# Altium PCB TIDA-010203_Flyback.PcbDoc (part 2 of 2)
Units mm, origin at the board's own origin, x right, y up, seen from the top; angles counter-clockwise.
Board outline 58 x 45 mm, 2 copper layers (Top Layer, Bottom Layer), stack 1.646 mm thick; 65 components, 31 nets, 152 pads, 52 vias.
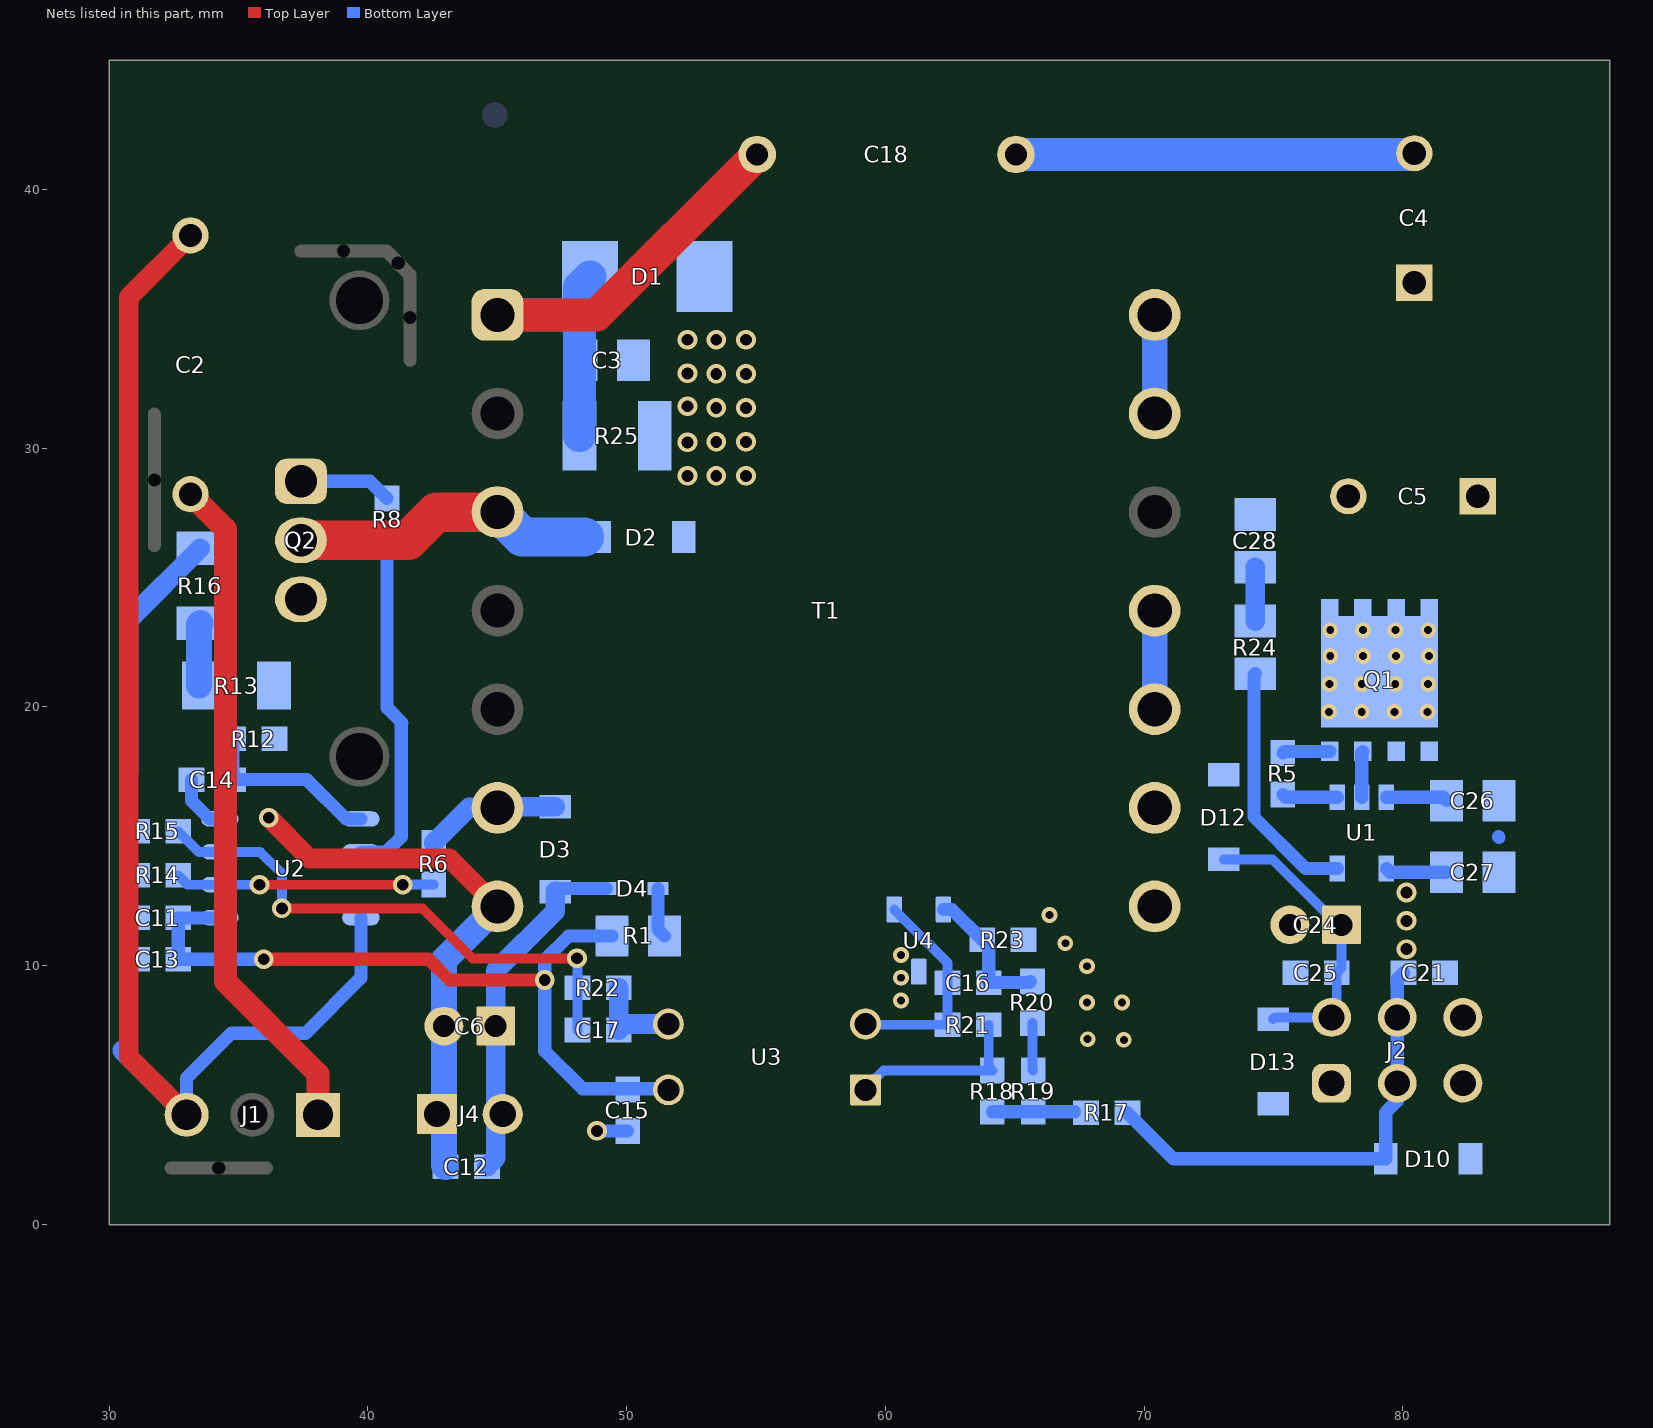
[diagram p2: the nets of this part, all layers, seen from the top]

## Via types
v1: diameter 0.762, hole 0.457, Top Layer to Bottom Layer, tented both sides, 26 vias
v2: diameter 0.61, hole 0.305, Top Layer to Bottom Layer, tented both sides, 26 vias

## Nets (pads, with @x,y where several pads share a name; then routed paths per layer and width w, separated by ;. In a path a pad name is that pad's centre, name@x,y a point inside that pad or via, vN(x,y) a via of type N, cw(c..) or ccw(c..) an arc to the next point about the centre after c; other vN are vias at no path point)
5V_ISO: C24.1 C25.1 D12.1 D13.1 J2.2 | length 11.6
  Bottom Layer w0.381: D12.1@73.076,14.111 74.966,14.111 77.494,11.582 C24.1@77.632,11.582 77.632,9.915 C25.1@77.445,9.728 77.445,8.204 J2.2@77.241,8.001 75.045,8.001 D13.1@74.981,7.937
12V: C6.1 C12.1 D3.1 D4.2 J4.2 | length 13.7
  Bottom Layer w0.508: D3.1@47.244,12.866 47.357,12.979 D4.2@49.216,12.979
  Bottom Layer w0.762: C12.1@44.602,2.235 44.942,2.575 C6.1@44.942,7.671 44.942,9.814 47.244,12.116 D3.1@47.244,12.866
12V_ISO: C4.1 C5.1 C21.1 C27.1 D10.1 J2.3 J2.4 R17.1 T1.13 T1.14 U1.4 | length 24.4
  Bottom Layer w0.508: R17.1@69.355,4.318 71.133,2.54 D10.1@79.338,2.54 79.338,4.332 79.781,4.775 J2.3@79.781,5.461 J2.4@79.781,8.001 79.781,9.487 C21.1@80.023,9.728 ; U1.4@79.36,13.763 79.509,13.614 C27.1@81.686,13.614
  Bottom Layer w1: T1.13@70.409,31.344 T1.14@70.409,35.154
  other v1: 80.137,10.643 80.137,11.735 80.137,12.827
NetC3_2: C3.2 D1.1 D2.1 R25.1
  other v1: 52.349,28.931 53.467,28.931 54.61,28.931 52.349,30.226 53.467,30.245 54.61,30.245 53.467,31.559 54.61,31.559 52.349,31.623 53.467,32.874 54.61,32.874 52.349,32.893 52.349,34.188 53.467,34.188 54.61,34.188
NetC14_1: C14.1 R12.1 U2.5 | length 7.2
  Bottom Layer w0.508: R12.1@34.785,18.771 C14.1@34.785,17.196 37.643,17.196 39.167,15.672 U2.5@39.733,15.672
NetC16_1: C16.1 R20.1 R23.1 U4.2 | length 5.4
  Bottom Layer w0.508: U4.2@62.24,12.173 62.567,12.173 R23.1@63.741,10.998 63.995,10.744 C16.1@63.995,9.347 65.57,9.347 R20.1@65.608,9.385
NetC16_2: C16.2 R21.1 U3.2 U4.1 | length 8.5
  Bottom Layer w0.381: U3.2@59.233,7.747 59.258,7.722 R21.1@62.395,7.722 C16.2@62.395,9.347 62.395,10.118 U4.1@60.34,12.173
NetC17_2: C17.2 R22.2 U3.3 | length 3.6
  Bottom Layer w0.762: R22.2@49.695,9.144 C17.2@49.695,7.518 49.924,7.747 U3.3@51.613,7.747
NetC26_1: C26.1 U1.3 | length 2.4
  Bottom Layer w0.508: U1.3@79.36,16.513 81.556,16.513 C26.1@81.686,16.383
NetC28_1: C28.1 R24.1 | length 2.1
  Bottom Layer w0.762: R24.1@74.295,23.317 C28.1@74.295,25.4
NetD2_2: D2.2 Q2.2 T1.3 | length 11.8
  Top Layer w1.524: Q2.2@37.414,26.441 41.554,26.441 42.647,27.534 T1.3@45.009,27.534
  Bottom Layer w1.524: T1.3@45.009,27.534 45.974,26.568 48.361,26.568
NetD4_1: D4.1 R1.1 | length 1.9
  Bottom Layer w0.508: D4.1@51.216,12.979 51.216,11.395 R1.1@51.46,11.151
NetD12_2: D12.2 T1.9
NetQ1_4: Q1.4 R5.2 | length 1.8
  Bottom Layer w0.508: R5.2@75.362,18.224 75.421,18.284 Q1.4@77.178,18.284
NetQ1_5: Q1.5 Q1.6 Q1.7 Q1.8 Q1.9 R24.2 T1.10 T1.11 U1.5 | length 13.4
  Bottom Layer w0.508: R24.2@74.295,21.285 74.244,21.234 74.244,15.748 76.229,13.763 U1.5@77.46,13.763
  Bottom Layer w1: T1.10@70.409,19.914 T1.11@70.409,23.724
  other v2: 77.14,19.812 78.41,19.812 79.68,19.812 80.95,19.812 77.165,20.883 78.41,20.883 79.705,20.883 80.976,20.883 77.191,21.971 78.461,21.971 79.731,21.971 81.001,21.971 77.191,22.968 78.452,22.968 79.714,22.968 80.976,22.968
NetQ2_1: Q2.1 R8.2 | length 3.6
  Bottom Layer w0.508: Q2.1@37.414,28.721 40.074,28.721 R8.2@40.742,28.054
NetQ2_3: Q2.3 R12.2 R13.2
NetR5_1: R5.1 U1.1 | length 2.1
  Bottom Layer w0.508: R5.1@75.362,16.624 75.473,16.513 U1.1@77.46,16.513
NetR6_1: R6.1 R14.2 U2.2 | length 10
  Top Layer w0.381: v1(35.814,13.132) v1(41.351,13.132)
  Bottom Layer w0.381: R14.2@32.674,13.489 33.032,13.132 U2.2@34.283,13.132 v1(35.814,13.132) v1@35.839,13.132 ; v1(41.351,13.132) 41.364,13.145 R6.1@42.545,13.145
NetR8_1: R8.1 U2.6 | length 13.5
  Bottom Layer w0.508: U2.6@39.733,14.402 40.716,14.402 41.289,14.975 41.289,19.343 41.326,19.38 40.742,19.964 R8.1@40.742,26.454
NetR13_1: R13.1 R16.2 | length 2.4
  Bottom Layer w1.016: R13.1@33.475,20.828 33.475,23.186 R16.2@33.528,23.239
NetR17_2: R17.2 R18.1 R19.2 | length 3.2
  Bottom Layer w0.508: R18.1@64.135,4.356 R19.2@65.71,4.356 R17.2@67.31,4.356
NetR18_2: R18.2 R21.2 U3.1 | length 7.1
  Bottom Layer w0.381: U3.1@59.233,5.207 59.182,5.207 59.931,5.956 R18.2@64.135,5.956 63.995,6.096 R21.2@63.995,7.722
NetR19_1: R19.1 R20.2 | length 1.8
  Bottom Layer w0.381: R20.2@65.684,7.785 65.684,5.982 R19.1@65.71,5.956
PGND: C2.2 C6.2 C11.2 C12.2 C13.2 C14.2 C15.2 J1.1 J4.1 R14.1 R15.1 R16.1 T1.7 U2.4 | length 60.4
  Top Layer w0.762: v1(36.17,15.723) 37.744,14.148 43.155,14.148 T1.7@45.009,12.294
  Top Layer w0.889: C2.2@33.147,28.223 34.493,26.877 34.493,9.398 38.075,5.817 J1.1@38.075,4.242
  Bottom Layer w0.508: C14.2@33.185,17.196 33.185,16.37 33.884,15.672 U2.4@34.283,15.672 ; v1(48.857,3.62) C15.2@50.038,3.62
  Bottom Layer w0.762: 30.759,17.475 30.759,23.37 R16.1@33.528,26.139
  Bottom Layer w1.016: C12.2@43.002,2.235 42.942,2.295 C6.2@42.942,7.671 42.942,10.227 T1.7@45.009,12.294
SGND: C4.2 C5.2 C18.1 C21.2 C26.2 C27.2 C28.2 D10.2 J2.5 J2.6 Q1.1 Q1.2 Q1.3 R23.2 U1.2 U4.3 | length 17.2
  Bottom Layer w0.508: U1.2@78.41,16.513 78.41,18.237 Q1.3@78.456,18.284 ; C4.2@80.395,41.351 C4.2@80.442,41.398 ; 83.693,14.986 83.718,14.961
  Bottom Layer w1.27: C18.1@65.046,41.351 C4.2@80.395,41.351
  other v2: 69.215,7.137 67.818,7.163 67.793,8.585 69.139,8.585 60.604,8.661 60.604,9.538 67.793,9.982 60.604,10.414 66.954,10.871 66.345,11.963
SGND2: C24.2 C25.2 D13.2 J2.1 T1.8
VAUX: D3.2 R6.2 T1.6 | length 5.3
  Bottom Layer w0.762: R6.2@42.545,14.745 43.917,16.116 44.996,16.116 T1.6@45.009,16.104 45.046,16.141 D3.2@47.244,16.141
VDCBUS+: C2.1 C3.1 C18.2 D1.2 J1.3 R25.2 T1.1 U2.8 | length 73.7
  Top Layer w0.762: J1.3@32.995,4.242 30.759,6.477 30.759,35.836 C2.1@33.147,38.223
  Top Layer w1.27: T1.1@45.009,35.154 48.848,35.154 C18.2@55.046,41.351
  Bottom Layer w0.508: J1.3@32.995,4.242 32.995,5.664 34.724,7.394 37.595,7.394 39.733,9.532 U2.8@39.733,11.862
  Bottom Layer w0.762: 30.505,6.731 J1.3@32.995,4.242
  Bottom Layer w1.27: T1.1@45.009,35.154 47.981,35.154 D1.2@48.182,35.355 ; R25.2@48.182,30.48 D1.2@48.182,35.355 ; D1.2@48.59,36.627 48.182,36.218 D1.2@48.182,35.355
VDD: C11.1 C13.1 C15.1 R1.2 U2.1 U3.4 | length 29.6
  Top Layer w0.508: v1(35.98,10.25) 42.353,10.25 43.155,9.449 v1(46.838,9.449)
  Bottom Layer w0.508: U2.1@34.283,11.862 34.271,11.85 C11.1@32.675,11.85 C13.1@32.675,10.25 v1(35.98,10.25) ; R1.2@49.428,11.151 47.76,11.151 46.838,10.228 v1(46.838,9.449) 46.838,6.706 48.298,5.245 51.575,5.245 U3.4@51.613,5.207
VFB: C17.1 R15.2 R22.1 U2.3 | length 21
  Top Layer w0.381: v1(36.678,12.217) 42.113,12.217 44.044,10.287 v1(48.082,10.287)
  Bottom Layer w0.381: R15.2@32.674,15.191 33.464,14.402 U2.3@34.283,14.402 35.839,14.402 36.678,13.564 v1(36.678,12.217) ; v1(48.082,10.287) 48.095,10.274 R22.1@48.095,9.144 C17.1@48.095,7.518
pads on no net: FID1.1 HS1.1 HS1.2 J1.2 T1.2 T1.4 T1.5 T1.12

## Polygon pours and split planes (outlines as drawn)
PGND on Top Layer "PGND_L01_P012" (solid, pour order 12): 45.136,11.379 48.895,11.379 48.895,9.144 48.463,9.144 47.854,8.534 41.123,8.534 41.148,8.509 41.148,1.854 51.308,1.854 51.41,1.956 51.41,13.183 44.907,13.183 44.552,12.827 44.552,12.243
12V_ISO on Top Layer "12V_ISO_L01_P000" (solid, pour order 0): 69.19,30.455 69.19,37.516 69.266,37.592 86.487,37.592 86.487,11.227 85.217,9.957 82.245,9.957 82.245,27.965 79.781,30.429
SGND on Bottom Layer "Top Layer-No Net" (solid, pour order 2): 73.533,27.991 73.508,28.016 73.508,37.592 86.512,37.592 86.335,37.414 86.335,1.727 82.677,1.727 82.296,2.108 82.296,8.738 81.356,9.677 81.356,10.846 83.566,13.056 83.566,17.221 83.414,17.221 82.245,18.39 82.321,18.466 82.321,25.806 77.191,25.806 76.022,26.975 74.676,26.975

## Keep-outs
Keep-Out Layer:
  text ".Layer_Name" at -20.904,-46.571 h1.52

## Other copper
Top Layer:
  rectangle net NetD2_2: 41.554,25.654 45.923,27.432
  region net PGND: 42.088,15.773 46.152,13.132 46.152,12.878 46.152,12.344 44.628,12.344 43.84,13.132
  region net PGND: 42.443,13.868 44.094,12.217 44.094,12.065 44.729,12.065 44.983,12.319 42.951,14.351 42.951,14.376
  region net PGND: 36.17,15.723 36.22,15.773 42.088,15.773 43.409,14.453 43.155,14.199 43.155,14.148 37.744,14.148
  region net NetC3_2: 50.444,34.493 51.968,36.017 52.019,35.966 55.296,35.966 55.296,25.222 55.27,25.197 51.613,25.197 51.613,27.889 51.638,27.915 50.444,29.108
  region net NetD2_2: 41.377,25.806 42.342,26.772 45.212,26.772 45.212,27.381 44.882,27.711 44.78,27.61 42.215,27.61
  region net 12V_ISO: 82.372,12.116 80.67,12.116 78.816,10.262 78.816,4.623 78.791,4.597 78.791,4.496 78.791,4.013 80.874,4.013 80.874,9.042 81.305,9.347 82.55,10.16
  region net 12V_ISO: 82.692,15.875 82.448,15.875 79.502,12.929 79.502,10.465 82.169,10.465 82.956,11.252
  region net SGND: 82.296,8.865 82.296,3.378 75.514,3.378 75.514,10.185 75.463,10.236 69.088,10.236 66.319,13.005 60.249,13.005 60.249,1.346 60.325,1.27 86.258,1.27 86.258,8.839
  region net NetQ1_5: 69.139,21.438 69.139,18.796 72.898,18.796 74.994,16.7 81.407,16.7 81.407,24.994 76.2,24.994 76.175,24.968 76.175,22.606 75.413,22.606 74.244,21.438
  region net NetQ1_5: 76.2,24.994 72.111,20.904 76.175,20.904 76.276,20.803
  region net VDCBUS+: 32.614,37.821 32.614,37.567 32.868,37.313 33.63,37.313 34.722,38.405 43.459,38.405 43.739,38.125 43.739,33.96 46.253,33.96 46.228,33.985 46.228,38.659 46.177,38.659 44.526,40.31 34.392,40.31 34.366,40.284 33.096,40.284 32.156,39.345 32.156,37.719 32.487,37.389
  text ".Layer_Name" at -20.904,-46.571 h1.52
Bottom Layer:
  rectangle net SGND: 78.13,17.526 84.353,18.669
  rectangle net PGND: 30.404,9.55 31.547,17.882
  region net PGND: 33.35,16.307 31.191,16.307 31.14,16.358 31.14,16.662 33.35,16.662
  region net PGND: 33.63,16.764 34.442,15.951 33.731,15.951 33.706,15.926 33.223,16.408 33.223,16.84
  region net PGND: 33.198,25.502 33.541,25.502 31.686,23.508 31.471,23.724 31.445,23.749
  region net PGND: 33.697,27.347 30.378,23.647 30.378,23.419 30.711,23.419 30.93,23.2
  region net NetC3_2: 53.01,36.627 52.603,36.627 50.444,34.468 50.444,29.108 52.426,27.127 52.426,25.273 52.502,25.197 55.27,25.197 55.27,37.998 55.245,38.024 53.035,38.024
  region net NetD2_2: 44.882,27.711 48.565,27.711 48.565,26.848 48.463,26.949 45.796,26.949
  region net NetQ1_5: 73.749,21.882 72.161,21.641 69.139,21.285 69.139,21.082 69.19,21.031 72.898,21.031
  region net NetQ1_5: 72.542,21.361 72.466,21.285 69.139,21.285 69.139,18.847 69.113,18.821 69.139,18.796 72.898,18.796 72.898,18.898 73.914,19.914
  region net NetQ1_5: 70.409,19.914 70.942,19.914 72.746,21.717 80.112,21.717 80.645,21.184 80.645,19.228 70.409,19.228 70.18,19.456
  region net NetD12_2: 73.787,17.678 69.367,17.678 69.367,15.24 71.45,15.24 72.695,16.51 73.063,16.954 72.923,17.297 72.974,17.348
  region net PGND: 31.699,24.31 31.699,17.196 30.607,18.288 30.607,23.218
  region net PGND: 32.487,29.007 34.214,29.007 34.646,28.575 34.646,25.527 32.487,25.527 32.461,25.502
  region net NetQ2_3: 35.916,18.364 35.916,25.019 35.941,25.044 35.992,24.994 38.481,24.994 38.481,20.98 37.744,20.244 37.744,18.364
  region net SGND: 82.321,19.057 82.321,18.034 83.083,17.272 83.083,12.548 83.058,12.522 83.668,11.913 85.801,11.913 85.801,19.533 85.547,19.787
  region net 12V_ISO: 81.686,13.614 81.661,13.589 81.661,12.37 80.518,11.227 80.518,9.728 79.629,9.728 79.578,9.677 79.509,9.747 79.509,13.614
  region net SGND2: 70.358,9.601 70.358,13.284 75.59,12.319 76.276,11.633 76.276,9.601 75.844,9.601
  region net SGND2: 70.358,11.506 74.092,11.506 73.812,11.227 73.812,5.867 77.064,5.867 77.572,5.359 77.572,4.318 73.152,4.318 70.358,7.112
  region net SGND: 77.521,37.567 83.49,37.567 83.49,44.094 83.414,44.171 77.546,44.171
  region net SGND: 61.29,10.312 60.655,10.947 60.3,10.947 60.3,8.331 60.376,8.255 60.808,8.255 61.29,8.738
  region net NetQ1_5: 74.981,21.869 75.489,21.869 76.378,22.758 76.378,24.968 81.407,24.968 81.306,20.371 74.905,20.371 74.879,20.396
  region net SGND: 64.922,12.319 64.922,10.897 65.938,10.897 66.904,9.931 66.904,5.74 69.977,5.74 69.977,9.804 69.113,9.804 66.599,12.319
  region net SGND: 65.405,10.541 66.954,10.541 66.294,11.201 65.684,11.201
  region net PGND: 34.442,15.875 34.62,15.951 35.342,16.267 36.678,16.267 36.678,15.113 34.773,15.113 34.493,15.392
  region net PGND: 31.369,17.551 32.83,17.551 33.185,17.196 33.02,17.031 33.02,16.51 31.293,16.51 31.14,16.662
  text ".Layer_Name" at -20.904,-46.571 h1.52

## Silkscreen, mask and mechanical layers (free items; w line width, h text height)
Top Overlay:
  text "5V 12V RT12" at 81.001,10.795 h0.64
  text "RT5 12V RT12" at 80.391,9.474 h0.64
  text "12VDC-0.25A" at 47.066,2.032 h0.64
  text "60W_AUX_E1" at 56.49,1.295 h1.52
  text ".Layer_Name" at -20.904,-46.571 h1.52
Bottom Overlay:
  circle w0.2: c34.646,10.795 r0.205
  lines w0.152: 32.69,7.036 32.69,6.706 ; 33.02,6.706 32.69,6.706 ; 33.198,9.373 33.198,7.214 32.69,6.706
  text ".Layer_Name" at -20.904,-46.571 h1.52
Top Paste:
  text ".Layer_Name" at -20.904,-46.571 h1.52
Bottom Paste:
  text ".Layer_Name" at -20.904,-46.571 h1.52
Top Solder:
  text ".Layer_Name" at -20.904,-46.571 h1.52
  text ".Layer_Name" at -20.904,-46.571 h1.52
Bottom Solder:
  text ".Layer_Name" at -20.904,-46.571 h1.52
Drill Guide:
  text ".Layer_Name" at -20.904,-46.571 h1.52
M1 Board Outline:
  the board outline again, w0.254
M2 Board Dimensions:
  rectangle: -35.56,-31.75 -32.385,-28.575
  rectangle: -32.385,-34.925 -22.86,-31.75
  lines w0.178: -35.56,-31.75 -10.16,-31.75 ; -32.385,-34.925 -32.385,-28.575 ; -29.21,-34.925 -29.21,-28.575 ; -22.86,-34.925 -22.86,-28.575 ; -16.51,-34.925 -16.51,-28.575 ; -35.56,-34.925 -10.16,-34.925 -10.16,-28.575 -35.56,-28.575 -35.56,-34.925
M3 3D STEP Top:
  text ".Layer_Name" at -20.904,-46.571 h1.52
M4 3D STEP Bottom:
  text ".Layer_Name" at -20.904,-46.571 h1.52
M5 Assembly Top:
  circle w0.2: c42.443,2.032 r0.17
  circle w0.2: c31.521,4.039 r0.24
  lines w0.254: -42.977,-48.391 124.663,-48.391 ; -42.977,-43.227 124.714,-43.227 ; -42.977,-38.062 -42.977,-53.556 58.75,-53.556 124.714,-53.556 124.714,-38.062 -42.964,-38.062 -42.964,-53.556 -2.946,-53.556 ; 19.634,-53.556 19.634,-38.062 ; 51.816,-43.227 51.816,-38.062 ; 73.152,-43.227 73.152,-38.062 ; 88.951,-53.721 88.951,-48.569
  text "COMPONENTS MARKED 'DNP' SHOULD NOT BE POPULATED." at -6.261,-32.855 h1.52
  text "ASSEMBLY VARIANT:" at -6.274,-35.789 h1.52
  text ".VariantName" at 20.041,-35.789 h1.52
  text "PCB VIEWED FROM TOP SIDE" at -41.364,-41.419 h1.52
  text "BOARD #:" at 21.539,-41.419 h1.52
  text ".PRJ_Number" at 35.395,-41.419 h1.52
  text "REV:" at 56.845,-41.419 h1.52
  text ".PCB_Rev" at 64.249,-41.419 h1.52
  text "SVN REV:" at 78.13,-41.419 h1.52
  text ".VersionControl_RevNumber" at 90.983,-41.419 h0.76
  text ".layer_Name" at -38.075,-46.558 h1.52
  text "TID #:" at 21.539,-46.584 h1.52
  text ".TID" at 35.395,-46.584 h1.52
  text "PLOT NAME =" at -41.364,-51.799 h1.52
  text ".plot_File_Name" at -20.904,-51.799 h1.52
  text "GENERATED    :" at 21.59,-51.799 h1.52
  text ".Print_Date" at 43.675,-51.799 h1.52
  text ".Print_Time" at 62.192,-51.799 h1.52
  text "TEXAS INSTRUMENTS" at 94.31,-51.799 h1.52
M6 Assembly Bottom:
  circle w0.2: c56.617,13.868 r0.17
  circle w0.2: c35.941,11.938 r0.18
  lines w0.254: -42.989,-43.239 124.701,-43.239 ; -42.939,-48.404 124.701,-48.404 ; -7.226,-53.734 -7.226,-48.582 ; 8.572,-43.239 8.572,-38.075 ; 29.909,-43.239 29.909,-38.075 ; 62.09,-53.569 62.09,-38.075 ; 84.671,-53.569 124.689,-53.569 124.689,-38.075 -42.989,-38.075 -42.989,-53.569 22.974,-53.569 124.701,-53.569 124.701,-38.075
  text "COMPONENTS MARKED 'DNP' SHOULD NOT BE POPULATED." at 119.431,-32.842 h1.52
  text ".VariantName" at 92.913,-35.789 h1.52
  text "ASSEMBLY VARIANT:" at 119.304,-35.789 h1.52
  text ".VersionControl_RevNumber" at -9.258,-41.432 h0.76
  text "SVN REV:" at 3.594,-41.432 h1.52
  text ".PCB_Rev" at 17.475,-41.432 h1.52
  text "REV:" at 24.879,-41.432 h1.52
  text ".PRJ_Number" at 46.33,-41.432 h1.52
  text "BOARD #:" at 60.185,-41.432 h1.52
  text "PCB VIEWED FROM BOTTOM SIDE" at 123.088,-41.432 h1.52
  text ".TID" at 46.33,-46.596 h1.52
  text "TID #:" at 60.185,-46.596 h1.52
  text ".layer_Name" at 118.44,-46.685 h1.52
  text "TEXAS INSTRUMENTS" at -12.586,-51.812 h1.52
  text ".Print_Time" at 19.533,-51.812 h1.52
  text ".Print_Date" at 38.049,-51.812 h1.52
  text "GENERATED    :" at 60.134,-51.812 h1.52
  text ".plot_File_Name" at 102.629,-51.812 h1.52
  text "PLOT NAME =" at 123.088,-51.812 h1.52
M9 Title Sheet:
  drawing of 57 lines, arcs and shapes, not listed
  text "1" at -16.768,179.362 h1.78
  text "2" at 46.622,179.362 h1.78
  text "3" at 109.851,179.362 h1.78
  text "4" at 173.52,179.362 h1.78
  text "5" at 236.995,179.362 h1.78
  text "6" at 300.622,179.362 h1.78
  text "A" at -46.139,150.33 h1.78
  text "A" at 329.781,150.33 h1.78
  text "B" at -46.139,89.878 h1.78
  text "B" at 329.781,89.878 h1.78
  text "C" at -46.139,29.553 h1.78
  text "C" at 329.781,29.553 h1.78
  text "PROJECT TITLE:" at 252.565,-17.716 h1.14
  text ".PRJ_Title" at 253.835,-21.103 h1.78
  text "DESIGNED FOR:" at 252.565,-25.362 h1.14
  text ".PRJ_Customer" at 253.835,-28.918 h1.78
  text "D" at -46.139,-30.645 h1.78
  text "D" at 329.781,-30.645 h1.78
  text "FILE NAME:" at 252.565,-32.982 h1.14
  text ".PCB_File_Name_No_Path" at 253.835,-36.03 h1.78
  text "Texas Instruments (TI) and/or its licensors do not warrant the accuracy or completeness of this specification" at 126.34,-40.141 h1.14
  text "ENGINEER:" at 252.565,-40.348 h1.14
  text "LAYOUT BY:" at 290.792,-40.348 h1.14
  text "or any information contained therein. TI and/or its licensors do not warrant that this design will meet" at 125.197,-43.002 h1.14
  text ".PRJ_Engineer" at 253.835,-44.285 h1.78
  text ".PCB_Layout" at 292.075,-44.285 h1.78
  text "the specifications, will be suitable for your application or fit for any particular purpose, or will operate in" at 125.197,-45.864 h1.14
  text "ALTIUM DESIGNER VERSION:" at 290.792,-48.222 h1.14
  text "an implementation. TI and/or its licensors do not warrant that the design is production worthy. You should" at 125.197,-48.726 h1.14
  text "completely validate and test your design implementation to confirm the system functionality for your application." at 126.34,-51.587 h1.14
  text ".print_Scale" at 253.835,-51.608 h1.78
  text ".Application_BuildNumber" at 292.075,-51.608 h1.78
  text "1" at -16.768,-56.858 h1.78
  text "2" at 46.622,-56.858 h1.78
  text "3" at 109.851,-56.858 h1.78
  text "4" at 173.52,-56.858 h1.78
  text "5" at 236.995,-56.858 h1.78
  text "6" at 300.622,-56.858 h1.78
M10 Fab Notes:
  drawing of 173 lines, arcs and shapes, not listed
  text "DESIGN INFORMATION" at 278.816,132.74 h1.52
  text "MIN. TRACK WIDTH:" at 262.444,128.168 h1.52
  text "10" at 290.289,128.168 h1.52
  text "MIL" at 294.22,128.168 h1.52
  text "MIN. CLEARANCE:" at 262.444,124.816 h1.52
  text "8" at 290.373,124.739 h1.52
  text "MIL" at 294.118,124.333 h1.52
  text "MIN. VIA PAD SIZE:" at 262.444,121.463 h1.52
  text "24" at 289.527,121.463 h1.52
  text "MIL" at 294.22,121.463 h1.52
  text "0.111MM (4.39MIL)" at 280.097,117.863 h1.52
  text "EXTERNAL" at 300.101,117.831 h1.52
  text "MINIMUM ANNULAR RING" at 254.082,117.755 h1.52
  text "PER" at 259.162,114.757 h1.52
  text "IPC-D-275 CLASS 2 LEVEL C" at 264.75,114.757 h1.52
  text "MIL, HOLES" at 302.551,111.905 h1.52
  text "+/-" at 292.583,111.887 h1.52
  text "+/-" at 314.274,111.887 h1.52
  text "REGISTRATION TOLERANCES:" at 254.082,111.76 h1.52
  text "METAL" at 284.556,111.76 h1.52
  text "5" at 299.192,111.76 h1.52
  text "3" at 320.35,111.76 h1.52
  text "MIL" at 323.303,111.76 h1.52
  text "+/-" at 314.274,108.89 h1.52
  text "HOLE SIZE TOLERANCE (UNLESS OTHERWISE SPECIFIED):" at 254.082,108.763 h1.52
  text "3" at 320.35,108.763 h1.52
  text "MIL" at 323.303,108.763 h1.52
  text "MATERIAL:" at 252.183,103.443 h1.52
  text "FR-4 High Tg" at 277.239,99.878 h1.52
  text "FR-408" at 262.876,99.66 h1.52
  text "OTHER" at 300.671,99.66 h1.52
  text "X" at 273.304,99.568 h1.52
  text "63 MIL (1.6mm) +/-10%" at 271.007,95.527 h1.52
  text "THICKNESS:" at 254.082,95.419 h1.52
  text "X" at 267.751,95.419 h1.52
  text "OTHER" at 303.643,95.419 h1.52
  text "TOLERANCE:" at 254.082,91.405 h1.52
  text "X" at 275.4,91.405 h1.52
  text "ANSI IPC-6012 TYPE 3 CLASS 2" at 280.149,91.405 h1.52
  text "OTHER +/-" at 280.148,87.443 h1.52
  text "BOW & TWIST:" at 254.082,83.455 h1.52
  text "X" at 275.4,83.455 h1.52
  text "ANSI IPC-6012 TYPE 3 CLASS 2" at 280.149,83.455 h1.52
  text "OTHER +/-" at 280.148,79.429 h1.52
  text "DRILLING:" at 252.183,75.911 h1.52
  text "REFERENCE:" at 254.082,72.94 h1.52
  text "X" at 270.547,72.94 h1.52
  text "AS SHOWN" at 275.297,72.94 h1.52
  text "X" at 293.432,72.94 h1.52
  text "NC_DRILL FILES" at 296.912,72.94 h1.52
  text "PTH COPPER THICKNESS:" at 254.082,68.926 h1.52
  text "X" at 282.79,68.926 h1.52
  text "20-30 um" at 286.27,68.926 h1.52
  text "OTHER" at 304.481,68.926 h1.52
  text "BOARD FINISH:" at 252.183,64.888 h1.52
  text "SILKSCREEN:" at 256.125,61.891 h1.52
  text "X" at 280.224,61.891 h1.52
  text "TOP" at 283.425,61.891 h1.52
  text "X" at 293.178,61.891 h1.52
  text "BOTTOM" at 296.404,61.891 h1.52
  text "SILKSCREEN COLOR:" at 256.125,57.649 h1.52
  text "X" at 280.198,57.649 h1.52
  text "WHITE" at 283.425,57.649 h1.52
  text "OTHER" at 296.404,57.649 h1.52
  text "X" at 283.526,53.605 h1.52
  text "GREEN" at 286.752,53.605 h1.52
  text "OTHER" at 302.449,53.605 h1.52
  text "SOLDER RESIST COLOR:" at 256.125,53.331 h1.52
  text "X" at 283.526,49.287 h1.52
  text "MATTE" at 286.752,49.287 h1.52
  text "SEMI-GLOSS" at 302.438,49.271 h1.52
  text "IMMERSION GOLD (ENIG)" at 279.132,44.499 h1.52
  text "ENEPIG" at 313.106,44.415 h1.52
  text "SURFACE FINISH:" at 252.183,44.39 h1.52
  text "X" at 274.384,44.39 h1.52
  text "IMM. TIN/SILVER OR EQUIV" at 260.553,40.402 h1.52
  text "OTHER" at 296.912,40.402 h1.52
  text "ARRAY/PANEL:" at 252.183,35.856 h1.52
  text "CUT AND TRIM PER M1 BOARD OUTLINE" at 279.132,35.747 h1.52
  text "N.C. ROUTE" at 279.132,31.893 h1.52
  text "X" at 296.379,31.893 h1.52
  text "V. SCORE" at 301.129,31.893 h1.52
  text "CERTIFICATION:" at 252.183,28.413 h1.52
  text "MATERIALS AND WORKMANSHIP FOR ALL PCBS" at 270.598,28.413 h1.52
  text "TO MEET OR EXCEED THE REQUIREMENTS OF:" at 270.598,25.924 h1.52
  text "X" at 261.111,22.457 h1.52
  text "ANSI IPC-A-600F CLASS ->" at 264.642,22.457 h1.52
  text "X" at 306.274,22.457 h1.52
  text "2" at 309.295,22.457 h1.52
  text "1" at 301.294,22.419 h1.52
  text "3" at 318.286,22.419 h1.52
  text "X" at 281.788,18.406 h1.52
  text "RoHS" at 285.266,18.406 h1.52
  text "OTHER" at 301.634,18.406 h1.52
  text "PER ORDER" at 311.72,18.406 h1.52
  text "ALL BOARDS MUST MEET OR EXCEED UL94-V0 REQUIREMENTS." at 252.882,14.199 h1.52
  text "PCB MUST BEAR THE UL94V-0 UL REGISTERED MATERIAL ID NUMBER" at 252.882,11.151 h1.52
  text "ADDITIONAL REQUIREMENTS:" at 252.183,6.747 h1.52
  text "MICROSECTION:" at 254.082,3.826 h1.52
  text "YES" at 277.088,3.826 h1.52
  text "REQUIRED" at 298.97,-0.14 h1.52
  text "BARE BOARD ELEC. TEST:" at 254.082,-0.212 h1.52
  text "NONE" at 287.248,-0.212 h1.52
  text "X" at 295.744,-0.212 h1.52
  text "PER ORDER" at 314.006,-0.212 h1.52
M11 Gerber Information:
  lines w0.254: -42.977,-48.391 124.663,-48.391 ; -42.977,-43.227 124.714,-43.227 ; -42.977,-38.062 -42.977,-53.556 58.75,-53.556 124.714,-53.556 124.714,-38.062 -42.964,-38.062 -42.964,-53.556 -2.946,-53.556 ; 19.634,-53.556 19.634,-38.062 ; 51.816,-43.227 51.816,-38.062 ; 73.152,-43.227 73.152,-38.062 ; 88.951,-53.721 88.951,-48.569
  text "ALL ARTWORK VIEWED FROM TOP SIDE" at -41.364,-41.419 h1.52
  text "BOARD #:" at 21.539,-41.419 h1.52
  text ".PRJ_Number" at 35.395,-41.419 h1.52
  text "REV:" at 56.845,-41.419 h1.52
  text ".PCB_Rev" at 64.249,-41.419 h1.52
  text "SVN REV:" at 78.13,-41.419 h1.52
  text ".VersionControl_RevNumber" at 90.983,-41.419 h1.52
  text "LAYER NAME =" at -41.364,-46.571 h1.52
  text "TID #:" at 21.539,-46.584 h1.52
  text ".TID" at 35.395,-46.584 h1.52
  text "PLOT NAME =" at -41.364,-51.799 h1.52
  text ".plot_File_Name" at -20.904,-51.799 h1.52
  text "GENERATED    :" at 21.59,-51.799 h1.52
  text ".Print_Date" at 43.675,-51.799 h1.52
  text ".Print_Time" at 62.192,-51.799 h1.52
  text "TEXAS INSTRUMENTS" at 94.31,-51.799 h1.52
M12 Stackup:
  drawing of 191 lines, arcs and shapes, not listed
  text "Layer" at 211.493,164.986 h1.52
  text "Name" at 221.905,164.986 h1.52
  text "Material" at 245.52,164.986 h1.52
  text "Thickness" at 267.358,164.986 h1.52
  text "Constant" at 283.864,164.986 h1.52
  text "Board Layer Stack" at 298.339,164.986 h1.52
  text "1" at 211.493,161.938 h1.52
  text "Top Overlay" at 221.905,161.938 h1.52
  text "2" at 211.493,158.89 h1.52
  text "Top Solder" at 221.905,158.89 h1.52
  text "Solder Resist" at 245.52,158.89 h1.52
  text "0.40mil" at 267.358,158.89 h1.52
  text "3.5" at 283.864,158.89 h1.52
  text "3" at 211.493,155.842 h1.52
  text "Top Layer" at 221.905,155.842 h1.52
  text "Copper" at 245.52,155.842 h1.52
  text "2.80mil" at 267.358,155.842 h1.52
  text "4" at 211.493,152.794 h1.52
  text "Dielectric1" at 221.905,152.794 h1.52
  text "FR-4 High Tg" at 245.52,152.794 h1.52
  text "59.20mil" at 267.358,152.794 h1.52
  text "4.8" at 283.864,152.794 h1.52
  text "5" at 211.493,149.746 h1.52
  text "Bottom Layer" at 221.905,149.746 h1.52
  text "Copper" at 245.52,149.746 h1.52
  text "2.80mil" at 267.358,149.746 h1.52
  text "6" at 211.493,146.698 h1.52
  text "Bottom Solder" at 221.905,146.698 h1.52
  text "Solder Resist" at 245.52,146.698 h1.52
  text "0.40mil" at 267.358,146.698 h1.52
  text "3.5" at 283.864,146.698 h1.52
  text "7" at 211.493,143.65 h1.52
  text "Bottom Overlay" at 221.905,143.65 h1.52
M13 Component Bodies Top:
  text ".Layer_Name" at -20.904,-46.571 h1.52
M14 Component Bodies Bottom:
  text ".Layer_Name" at -20.904,-46.571 h1.52
M15 Courtyards Top:
  text ".Layer_Name" at -20.904,-46.571 h1.52
M16 Courtyards Bottom:
  text ".Layer_Name" at -20.904,-46.571 h1.52
Drill Drawing:
  circle w0.254: c90.191,63.127 r0.847
  lines w0.254: 89.344,58.471 91.038,58.471 91.038,60.164 89.344,60.164 89.344,58.471 ; 89.344,70.324 89.768,70.324 90.191,69.901 90.614,70.324 91.038,70.324 90.614,70.747 91.038,71.171 90.614,71.171 90.191,71.594 89.768,71.171 89.344,71.171 89.768,70.747 89.344,70.324 ; 89.344,105.884 91.038,105.884 90.191,104.191 89.344,105.884 ; 89.344,108.001 90.191,108.424 91.038,108.001 90.614,108.847 91.038,109.694 90.191,109.271 89.344,109.694 89.768,108.847 89.344,108.001
  lines w0.381: 87.826,57.328 251.356,57.328 ; 87.826,110.668 251.356,110.668 ; 101.818,53.518 101.818,114.478 ; 119.542,53.518 119.542,114.478 ; 153.721,53.518 153.721,114.478 ; 166.57,53.518 166.57,114.478 ; 185.209,53.518 185.209,114.478 ; 217.711,53.518 217.711,114.478 ; 87.826,53.518 251.356,53.518 251.356,114.478 87.826,114.478 87.826,53.518
  text "Symbol" at 90.112,111.811 h1.83
  text "Hit Count" at 102.961,111.811 h1.83
  text "Finished Hole Size" at 120.685,111.811 h1.83
  text "Plated" at 154.864,111.811 h1.83
  text "Hole Type" at 167.713,111.811 h1.83
  text "Physical Length" at 186.352,111.811 h1.83
  text "Rout Path Length" at 218.854,111.811 h1.83
  text "26" at 102.961,108.001 h1.52
  text "12.00mil (0.30480mm)" at 120.685,108.001 h1.52
  text "PTH" at 154.864,108.001 h1.52
  text "Round" at 167.713,108.001 h1.52
  text "-" at 186.352,108.001 h1.52
  text "-" at 218.854,108.001 h1.52
  text "26" at 102.961,104.191 h1.52
  text "18.00mil (0.45720mm)" at 120.685,104.191 h1.52
  text "PTH" at 154.864,104.191 h1.52
  text "Round" at 167.713,104.191 h1.52
  text "-" at 186.352,104.191 h1.52
  text "-" at 218.854,104.191 h1.52
  text "1" at 102.961,100.381 h1.52
  text "20.00mil (0.50800mm)" at 120.685,100.381 h1.52
  text "NPTH" at 154.864,100.381 h1.52
  text "Slot" at 167.713,100.381 h1.52
  text "70.00mil (1.77800mm)" at 186.352,100.381 h1.52
  text "50.00mil (1.27000mm)" at 218.854,100.381 h1.52
  text "E" at 89.373,100.127 h1.69
  text "2" at 102.961,96.571 h1.52
  text "20.00mil (0.50800mm)" at 120.685,96.571 h1.52
  text "NPTH" at 154.864,96.571 h1.52
  text "Slot" at 167.713,96.571 h1.52
  text "150.00mil (3.81000mm)" at 186.352,96.571 h1.52
  text "130.00mil (3.30200mm)" at 218.854,96.571 h1.52
  text "H" at 89.373,96.317 h1.69
  text "1" at 102.961,92.761 h1.52
  text "20.00mil (0.50800mm)" at 120.685,92.761 h1.52
  text "NPTH" at 154.864,92.761 h1.52
  text "Slot" at 167.713,92.761 h1.52
  text "165.00mil (4.19100mm)" at 186.352,92.761 h1.52
  text "145.00mil (3.68300mm)" at 218.854,92.761 h1.52
  text "N" at 89.373,92.507 h1.69
  text "1" at 102.961,88.951 h1.52
  text "20.00mil (0.50800mm)" at 120.685,88.951 h1.52
  text "NPTH" at 154.864,88.951 h1.52
  text "Slot" at 167.713,88.951 h1.52
  text "220.00mil (5.58800mm)" at 186.352,88.951 h1.52
  text "200.00mil (5.08000mm)" at 218.854,88.951 h1.52
  text "Q" at 89.373,88.697 h1.69
  text "10" at 102.961,85.141 h1.52
  text "33.47mil (0.85001mm)" at 120.685,85.141 h1.52
  text "PTH" at 154.864,85.141 h1.52
  text "Round" at 167.713,85.141 h1.52
  text "-" at 186.352,85.141 h1.52
  text "-" at 218.854,85.141 h1.52
  text "K" at 89.373,84.887 h1.69
  text "6" at 102.961,81.331 h1.52
  text "35.43mil (0.90000mm)" at 120.685,81.331 h1.52
  text "PTH" at 154.864,81.331 h1.52
  text "Round" at 167.713,81.331 h1.52
  text "-" at 186.352,81.331 h1.52
  text "-" at 218.854,81.331 h1.52
  text "L" at 89.373,81.077 h1.69
  text "6" at 102.961,77.521 h1.52
  text "39.37mil (1.00000mm)" at 120.685,77.521 h1.52
  text "PTH" at 154.864,77.521 h1.52
  text "Round" at 167.713,77.521 h1.52
  text "-" at 186.352,77.521 h1.52
  text "-" at 218.854,77.521 h1.52
  text "J" at 89.373,77.267 h1.69
  text "2" at 102.961,73.711 h1.52
  text "40.00mil (1.01600mm)" at 120.685,73.711 h1.52
  text "PTH" at 154.864,73.711 h1.52
  text "Round" at 167.713,73.711 h1.52
  text "-" at 186.352,73.711 h1.52
  text "-" at 218.854,73.711 h1.52
  text "M" at 89.373,73.457 h1.69
  text "3" at 102.961,69.901 h1.52
  text "45.67mil (1.15999mm)" at 120.685,69.901 h1.52
  text "PTH" at 154.864,69.901 h1.52
  text "Round" at 167.713,69.901 h1.52
  text "-" at 186.352,69.901 h1.52
  text "-" at 218.854,69.901 h1.52
  text "3" at 102.961,66.091 h1.52
  text "49.21mil (1.25001mm)" at 120.685,66.091 h1.52
  text "PTH" at 154.864,66.091 h1.52
  text "Round" at 167.713,66.091 h1.52
  text "-" at 186.352,66.091 h1.52
  text "-" at 218.854,66.091 h1.52
  text "R" at 89.373,65.837 h1.69
  text "14" at 102.961,62.281 h1.52
  text "51.97mil (1.31999mm)" at 120.685,62.281 h1.52
  text "PTH" at 154.864,62.281 h1.52
  text "Round" at 167.713,62.281 h1.52
  text "-" at 186.352,62.281 h1.52
  text "-" at 218.854,62.281 h1.52
  text "2" at 102.961,58.471 h1.52
  text "71.42mil (1.81399mm)" at 120.685,58.471 h1.52
  text "PTH" at 154.864,58.471 h1.52
  text "Round" at 167.713,58.471 h1.52
  text "-" at 186.352,58.471 h1.52
  text "-" at 218.854,58.471 h1.52
  text "103 Total" at 102.961,54.661 h1.52
  text "Slot definitions :" at 90.112,50.978 h1.52
  text "Rout Path Length" at 116.342,50.978 h1.52
  text "= Calculated from tool start centre position to tool end centre position." at 141.303,50.978 h1.52
  text "Physical Length" at 116.342,48.439 h1.52
  text "= Rout Path Length + Tool Size = Slot length as defined in the PCB layout" at 139.779,48.439 h1.52
  text "DRILL TABLE" at 104.089,-4.318 h1.52
  text "FOR 7.874MIL DRILL +0/-7.874MIL" at 104.089,-7.036 h1.52
  text "FOR 12MIL DRILL +0/-12MIL" at 104.115,-9.474 h1.52
  text "FOR PTH +3/-3MIL" at 104.089,-11.862 h1.52
  text "FOR NPTH +2/-2MIL" at 104.089,-14.529 h1.52
  text "Vias tented in both sides." at 104.089,-17.043 h1.52
  text "Copper thickness is 2oz." at 104.013,-19.66 h1.52
  text "This is not impedence controlled board." at 103.988,-22.581 h1.52
  text ".Layer_Name" at -20.904,-46.571 h1.52

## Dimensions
-35.56,-34.925 to -10.16,-34.925 on M2 Board Dimensions
88,0 to 30,0 on M2 Board Dimensions
29.972,0 to 30,45 on M2 Board Dimensions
